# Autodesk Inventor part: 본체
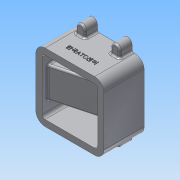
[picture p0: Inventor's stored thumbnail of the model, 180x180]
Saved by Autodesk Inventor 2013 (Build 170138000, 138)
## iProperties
Created: 2018-01
Part Number: 본체
Material: 알루미늄 6061
Document SubType Name: Modeling
Designer: Administrator
Density: 2.71 g/cm^3
Mass: 998.911 g
Surface Area: 834.406 cm^2
Volume: 368.602 cm^3
Author: Administrator
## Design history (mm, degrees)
sketch "스케치1"
  geometry: L1 (-55, 55)-(55, 55); L2 (55, 55)-(55, -55); L3 (55, -55)-(-55, -55); L4 (-55, -55)-(-55, 55); L5 (45, -45)-(45, 45); L6 (45, 45)-(-45, 45); L7 (-45, 45)-(-45, -45); L8 (-45, -45)-(45, -45); 3 further points
  constraints: 16 end point, 4 parallel, 2 midpoint, 2 perpendicular, 1 horizontal, 1 horizontal alignment, 1 vertical alignment, 3 other
  dimensions: "d0" = 110 distance of L1.start L1.end; "d2" = 110 distance of L1.end L2.end; "d3" = 10 distance between parallel lines of L2 L5
extrude "돌출1" new body sketch "스케치1" stored distance "d4" = 65; taper "d5" = 0 deg
sketch "스케치2"
  geometry: L1 (-55, -55)-(-55, 55) reference; L2 (-55, 55)-(55, 55) reference; L3 (55, 55)-(55, -55) reference; L4 (55, -55)-(-55, -55) reference; L5 (-35.5, 65)-(-35.5, 55); L6 (-20.5, 65)-(-20.5, 55); L7 (-35.5, 55)-(-20.5, 55); L8 (0, 0)-(0, 45); L9 (0, 0)-(45, 0); A1 r 7.5 centre (-28, 65) between (-20.5, 65) and (-35.5, 65)
  constraints: 10 end point, 2 perpendicular, 2 point on circle, 2 point on line, 2 tangent, 1 centre point, 1 collinear
  dimensions: "d6" = 15 diameter of A1; "d7" = 27 distance from line of A1.centre L1; "d8" = 10 distance from line of A1.centre L2
extrude "돌출2" join sketch "스케치2" distance "d9" = 20; taper "d10" = 0 deg
sketch "스케치3"
  geometry: L1 (-110, 65)-(0, 65) reference; C1 r 7.5 at (-55, 65); 2 further points
  constraints: 2 midpoint, 1 centre point, 1 vertical alignment
  dimensions: "d11" = 15 diameter of C1
extrude "돌출3" cut sketch "스케치3" distance "d12" = 19; taper "d13" = 0 deg
sketch "스케치4"
  geometry: L1 (-55, 55)-(-35.5, 55) reference; L2 (-35.5, 55)-(-35.5, 65) reference; L3 (-20.5, 65)-(-20.5, 55) reference; L4 (-20.5, 55)-(20.5, 55) reference; L5 (20.5, 55)-(20.5, 65) reference; L6 (35.5, 65)-(35.5, 55) reference; L7 (35.5, 55)-(55, 55) reference; L8 (55, 55)-(55, -55) reference; L9 (55, -55)-(35.5, -55) reference; L10 (35.5, -55)-(35.5, -65) reference; L11 (20.5, -65)-(20.5, -55) reference; L12 (20.5, -55)-(-20.5, -55) reference; L13 (-20.5, -55)-(-20.5, -65) reference; L14 (-35.5, -65)-(-35.5, -55) reference; L15 (-35.5, -55)-(-55, -55) reference; L16 (-55, -55)-(-55, -7.5) reference; L17 (-55, -7.5)-(-36, -7.5) reference; L18 (-36, -7.5)-(-36, 7.5) reference; L19 (-36, 7.5)-(-55, 7.5) reference; L20 (-55, 7.5)-(-55, 55) reference; L21 (-45, 45)-(45, 45); L22 (45, 45)-(45, -45); L23 (45, -45)-(-45, -45); L24 (-45, -45)-(-45, 45); L25 (-45, 25)-(35, 25); L26 (35, 25)-(35, -25); L27 (35, -25)-(-45, -25); L28 (-45, -25)-(-45, 25); A1 r 7.5 centre (-28, 65) between (-20.5, 65) and (-35.5, 65) reference; A2 r 7.5 centre (28, 65) between (35.5, 65) and (20.5, 65) reference; A3 r 7.5 centre (28, -65) between (20.5, -65) and (35.5, -65) reference; A4 r 7.5 centre (-28, -65) between (-35.5, -65) and (-20.5, -65) reference; 4 further points
  constraints: 16 end point, 4 parallel, 3 midpoint, 2 horizontal, 2 horizontal alignment, 2 perpendicular, 1 collinear, 1 vertical alignment
  dimensions: "d14" = 10 distance between parallel lines of L24 L20; "d15" = 10 distance between parallel lines of L21 L4; "d16" = 30 distance between parallel lines of L25 L4; "d17" = 20 distance between parallel lines of L8 L26
extrude "돌출4" cut sketch "스케치4" stored distance "d18" = 19; taper "d19" = 0 deg
sketch "스케치5"
  geometry: L1 (-100, 65)-(-100, 0) reference; L2 (-100, 0)-(-110, 0) reference; L3 (-110, 0)-(-110, 65) reference; L4 (-110, 65)-(-100, 65) reference; L5 (-10, 0)-(-10, 65) reference; L6 (-10, 65)-(0, 65) reference; L7 (0, 65)-(0, 0) reference; L8 (0, 0)-(-10, 0) reference; L9 (-62.5, 65)-(-47.5, 65) reference; L10 (-80, 65)-(-62.5, 65) reference; L11 (-80, 0)-(-80, 65) reference; L12 (-30, 0)-(-80, 0) reference; L13 (-30, 65)-(-30, 0) reference; L14 (-47.5, 65)-(-30, 65) reference; C1 r 16 at (-55, 65); A1 r 7.5 centre (-55, 65) between (-62.5, 65) and (-47.5, 65) reference; 1 further point
  constraints: 1 centre point, 1 coincident
  dimensions: "d20" = 32 diameter of C1
extrude "돌출5" cut sketch "스케치5" distance "d21" = 14; taper "d22" = 0 deg
sketch "스케치6"
  geometry: L1 (-71, 65)-(-39, 65) reference; L2 (-80, 65)-(-71, 65) reference; L3 (-80, 0)-(-80, 65) reference; L4 (-30, 0)-(-80, 0) reference; L5 (-30, 65)-(-30, 0) reference; L6 (-39, 65)-(-30, 65) reference; L7 (-10, 65)-(14.5, 65) reference; L8 (14.5, 65)-(14.5, 45) reference; L9 (14.5, 45)-(0, 45) reference; L10 (0, 45)-(0, 0) reference; L11 (0, 0)-(-10, 0) reference; L12 (-10, 0)-(-10, 65) reference; L13 (-110, 0)-(-110, 45) reference; L14 (-110, 45)-(-124.5, 45) reference; L15 (-124.5, 45)-(-124.5, 65) reference; L16 (-124.5, 65)-(-100, 65) reference; L17 (-100, 65)-(-100, 0) reference; L18 (-100, 0)-(-110, 0) reference; C1 r 20 at (-55, 65); A1 r 16 centre (-55, 65) between (-71, 65) and (-39, 65) reference; 1 further point
  constraints: 1 centre point, 1 coincident
  dimensions: "d23" = 40 diameter of C1
extrude "돌출6" cut sketch "스케치6" distance "d24" = 47; taper "d25" = 0 deg
sketch "스케치7"
  geometry: L1 (-75, 65)-(-35, 65) reference; L2 (-80, 65)-(-75, 65) reference; L3 (-80, 0)-(-80, 65) reference; L4 (-30, 0)-(-80, 0) reference; L5 (-30, 65)-(-30, 0) reference; L6 (-35, 65)-(-30, 65) reference; L7 (-126.874, 65)-(-100, 65) reference; L8 (-100, 65)-(-100, 0) reference; L9 (-100, 0)-(-110, 0) reference; L10 (-110, 0)-(-110, 45) reference; L11 (-110, 45)-(-126.874, 45) reference; L12 (-126.874, 45)-(-126.874, 65) reference; L13 (-10, 65)-(16.874, 65) reference; L14 (16.874, 65)-(16.874, 45) reference; L15 (16.874, 45)-(0, 45) reference; L16 (0, 45)-(0, 0) reference; L17 (0, 0)-(-10, 0) reference; L18 (-10, 0)-(-10, 65) reference; C1 r 15 at (-55, 65); A1 r 20 centre (-55, 65) between (-75, 65) and (-35, 65) reference; 1 further point
  constraints: 1 centre point, 1 coincident
  dimensions: "d26" = 30 diameter of C1
extrude "돌출7" cut sketch "스케치7" distance "d27" = 5; taper "d28" = 0 deg
sketch "스케치8"
  geometry: L1 (-10, 0)-(0, 0) reference; L2 (0, 0)-(80, 0) reference; L3 (80, 0)-(80, -65) reference; L4 (80, -65)-(0, -65) reference; L5 (0, -65)-(-10, -65) reference; L6 (-10, -65)-(-10, 0) reference; L7 (0, 0)-(0, -65) reference; L8 (90, 0)-(100, 0) reference; L9 (100, 0)-(100, -65) reference; L10 (100, -65)-(90, -65) reference; L11 (90, -65)-(90, 0) reference; L12 (80, -35)-(0, -56.436); L13 (0, -56.436)-(0, -65); L14 (0, -65)-(80, -65); L15 (80, -65)-(80, -35); 1 further point
  constraints: 8 end point, 3 collinear, 2 point on line
  dimensions: "d29" = 105 deg angle of L12 L7; "d30" = 30 distance from line of L12.start L10
extrude "돌출8" cut sketch "스케치8" stored distance "d31" = 5; taper "d32" = 0 deg
sketch "스케치9"
  geometry: L1 (35, -2.5)-(-45, -23.936) reference; L2 (20, -1.343)-(-55, -21.439); L3 (-17, 6.743)-(-55, -3.439); L4 (-55, 32.5)-(-55, -32.5) reference; L5 (-22, 16.5)-(-22, 32.5) reference; L6 (25, 17.5)-(25, 32.5) reference; L7 (-17, 6.743)-(-17, 32.5); L8 (20, -1.343)-(20, 32.5); L9 (-17, 32.5)-(20, 32.5); L10 (-55, -3.439)-(-55, -21.439); 1 further point
  constraints: 12 end point, 4 parallel, 2 point on line, 1 collinear, 1 perpendicular
  dimensions: "d33" = 5 distance between parallel lines of L2 L1; "d34" = 18 distance of L3.end L2.end; "d35" = 5 distance between parallel lines of L8 L6; "d36" = 5 distance between parallel lines of L5 L7; "d37" = 25.75698 distance of L3.start L7.end
extrude "돌출9" cut sketch "스케치9" stored distance "d38" = 30; taper "d39" = 0 deg
hole "구멍1" diameter "d42" = 3.242; stored, may be unused: countersink angle "d46" = 90 deg, drill point angle "d48" = 118 deg; dims "d40" = 10, "d41" = 10, "d43" = 9, "d44" = 4, "d45" = 2, "d47" = 11
sketch "스케치10"
  geometry: L1 (110, 0)-(0, 0) reference; L2 (0, 65)-(0, 0) reference; 2 further points
  constraints: 1 other
  dimensions: "d49" = 20 distance from line of point (55, 20) L1; "d50" = 55 distance from line of point (55, 20) L2
feature "엠보싱1" sketch "스케치10" dims "d0" = 110, "d2" = 110, "d3" = 10, "d51" = 0.5, "d52" = 0
fillet "모깎기1" dims "d53" = 15
fillet "모깎기2" dims "d54" = 5
fillet "모깎기4" dims "d56" = 1
chamfer "모따기1" distance "d57" = 1; stored, may be unused: second distance "d58" = 2, angle "d59" = 45 deg
fillet "모깎기5" dims "d60" = 3
fillet "모깎기6" dims "d61" = 3
fillet "모깎기7" dims "d62" = 3
fillet "모깎기8" dims "d63" = 3
fillet "모깎기10" dims "d65" = 3
fillet "모깎기11" dims "d66" = 3
fillet "모깎기12" dims "d67" = 3
fillet "모깎기13" dims "d68" = 3
node "솔리드1"
mirror "대칭1"
mirror "대칭2"
mirror "대칭3"
mirror "대칭4"
node "절단 모서리 투영1"
node "절단 모서리 투영2"
node "절단 모서리 투영3"
node "절단 모서리 투영4"
node "절단 모서리 투영5"
node "절단 모서리 투영6"
